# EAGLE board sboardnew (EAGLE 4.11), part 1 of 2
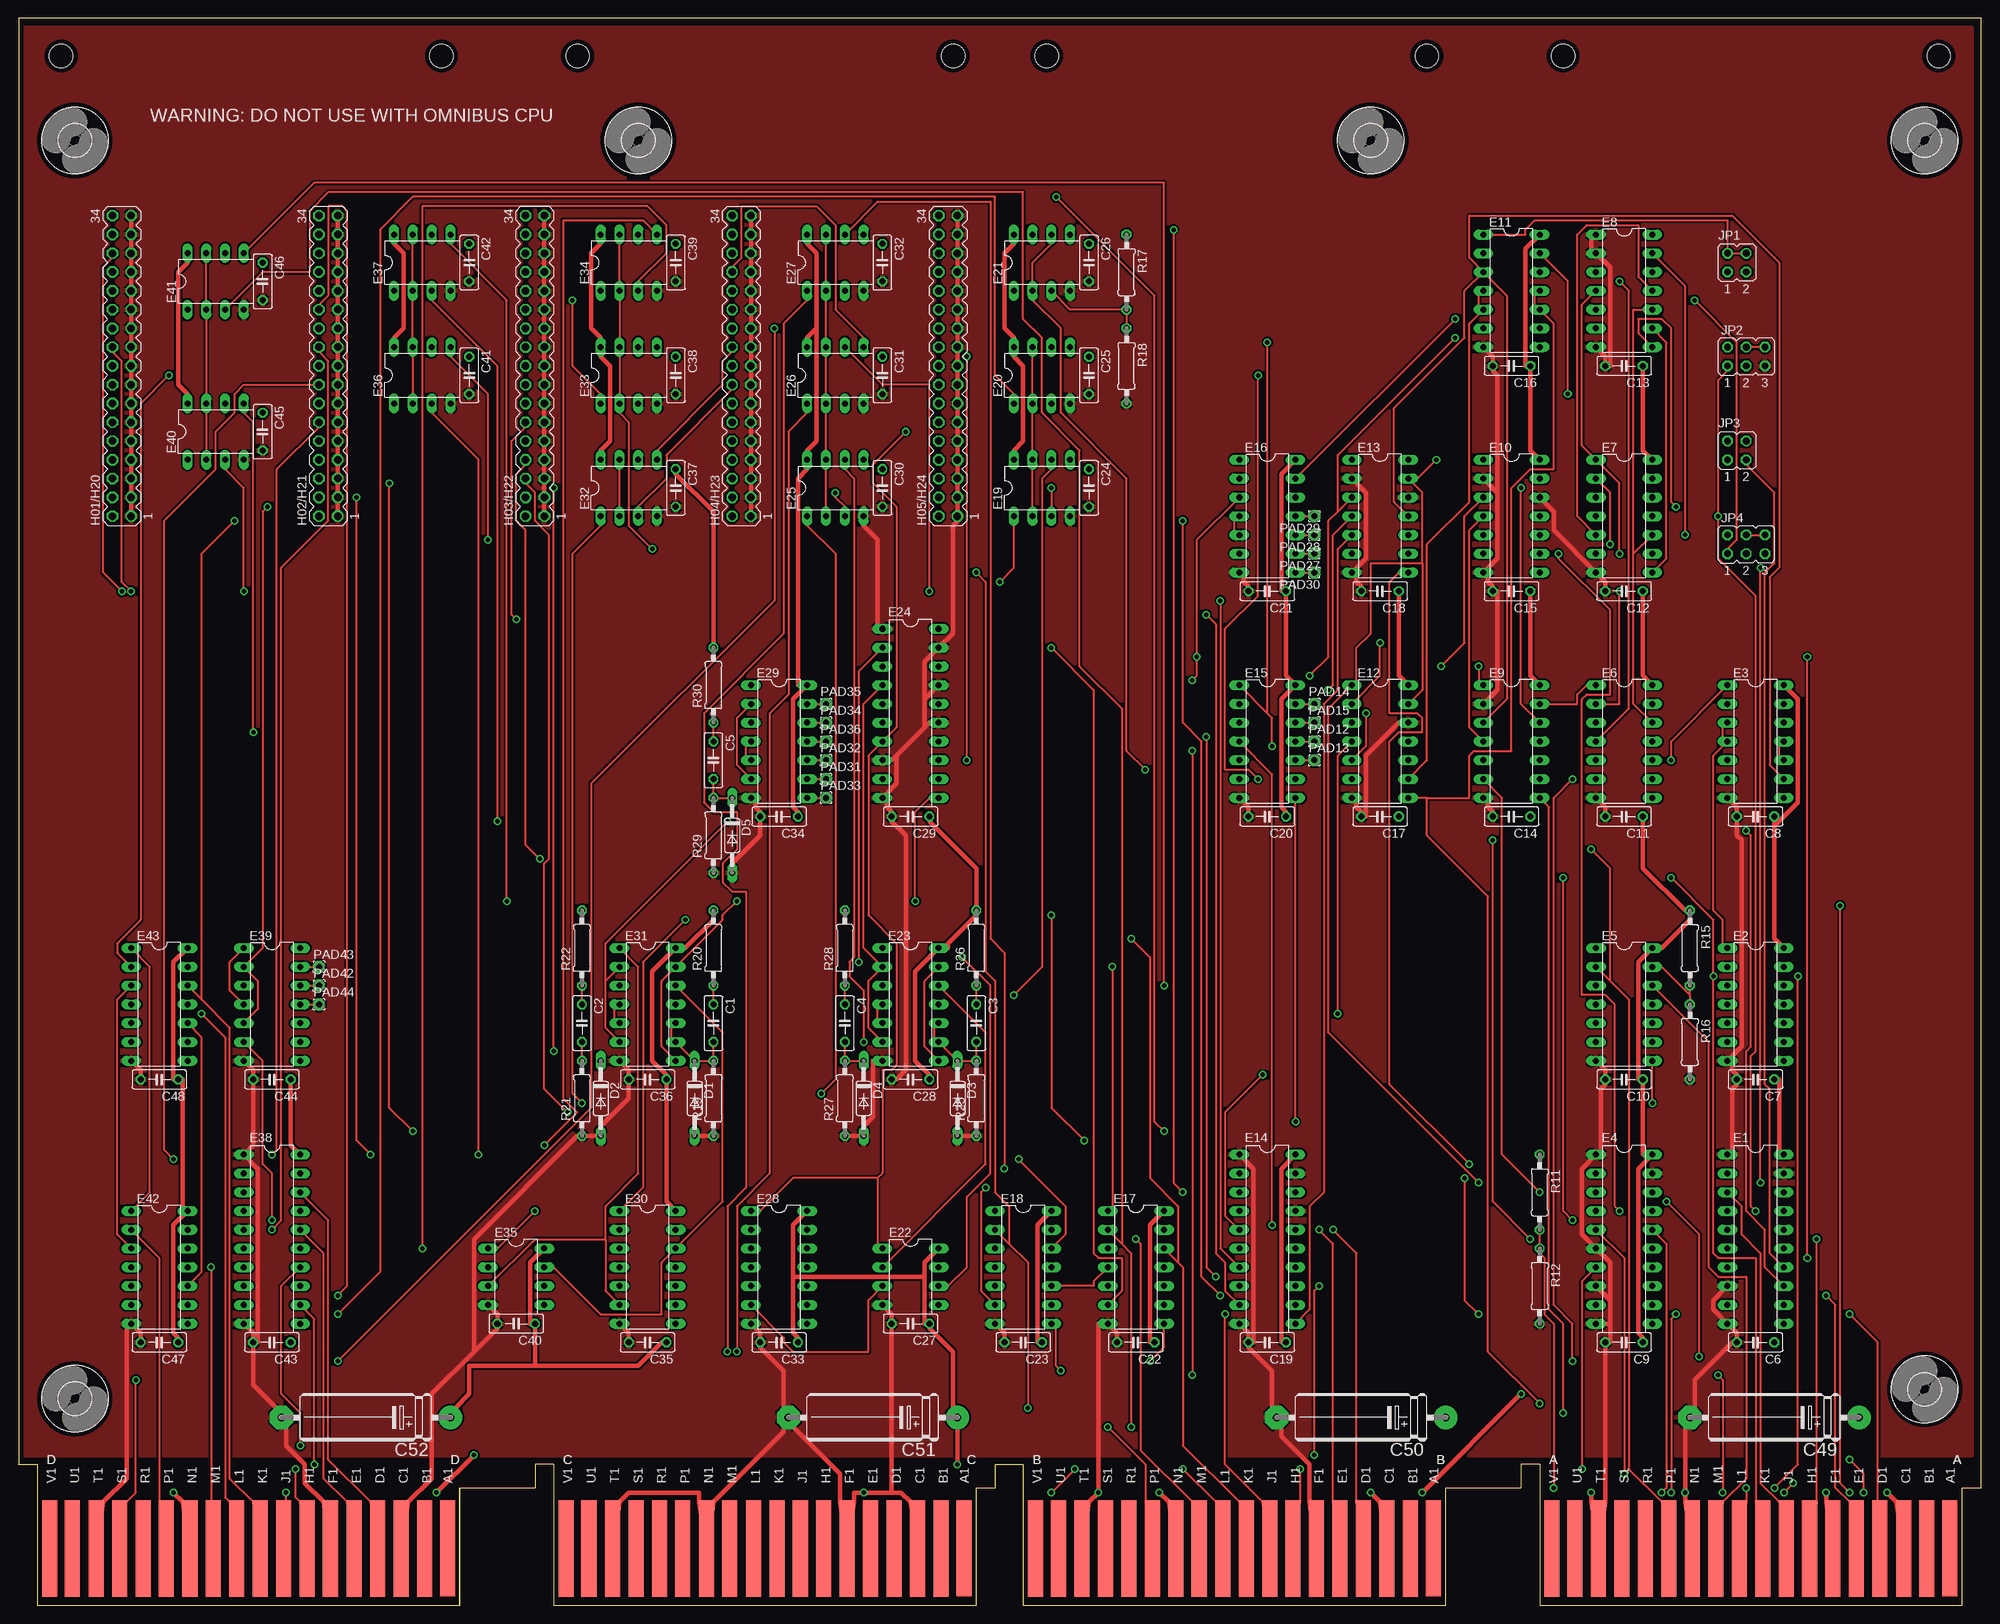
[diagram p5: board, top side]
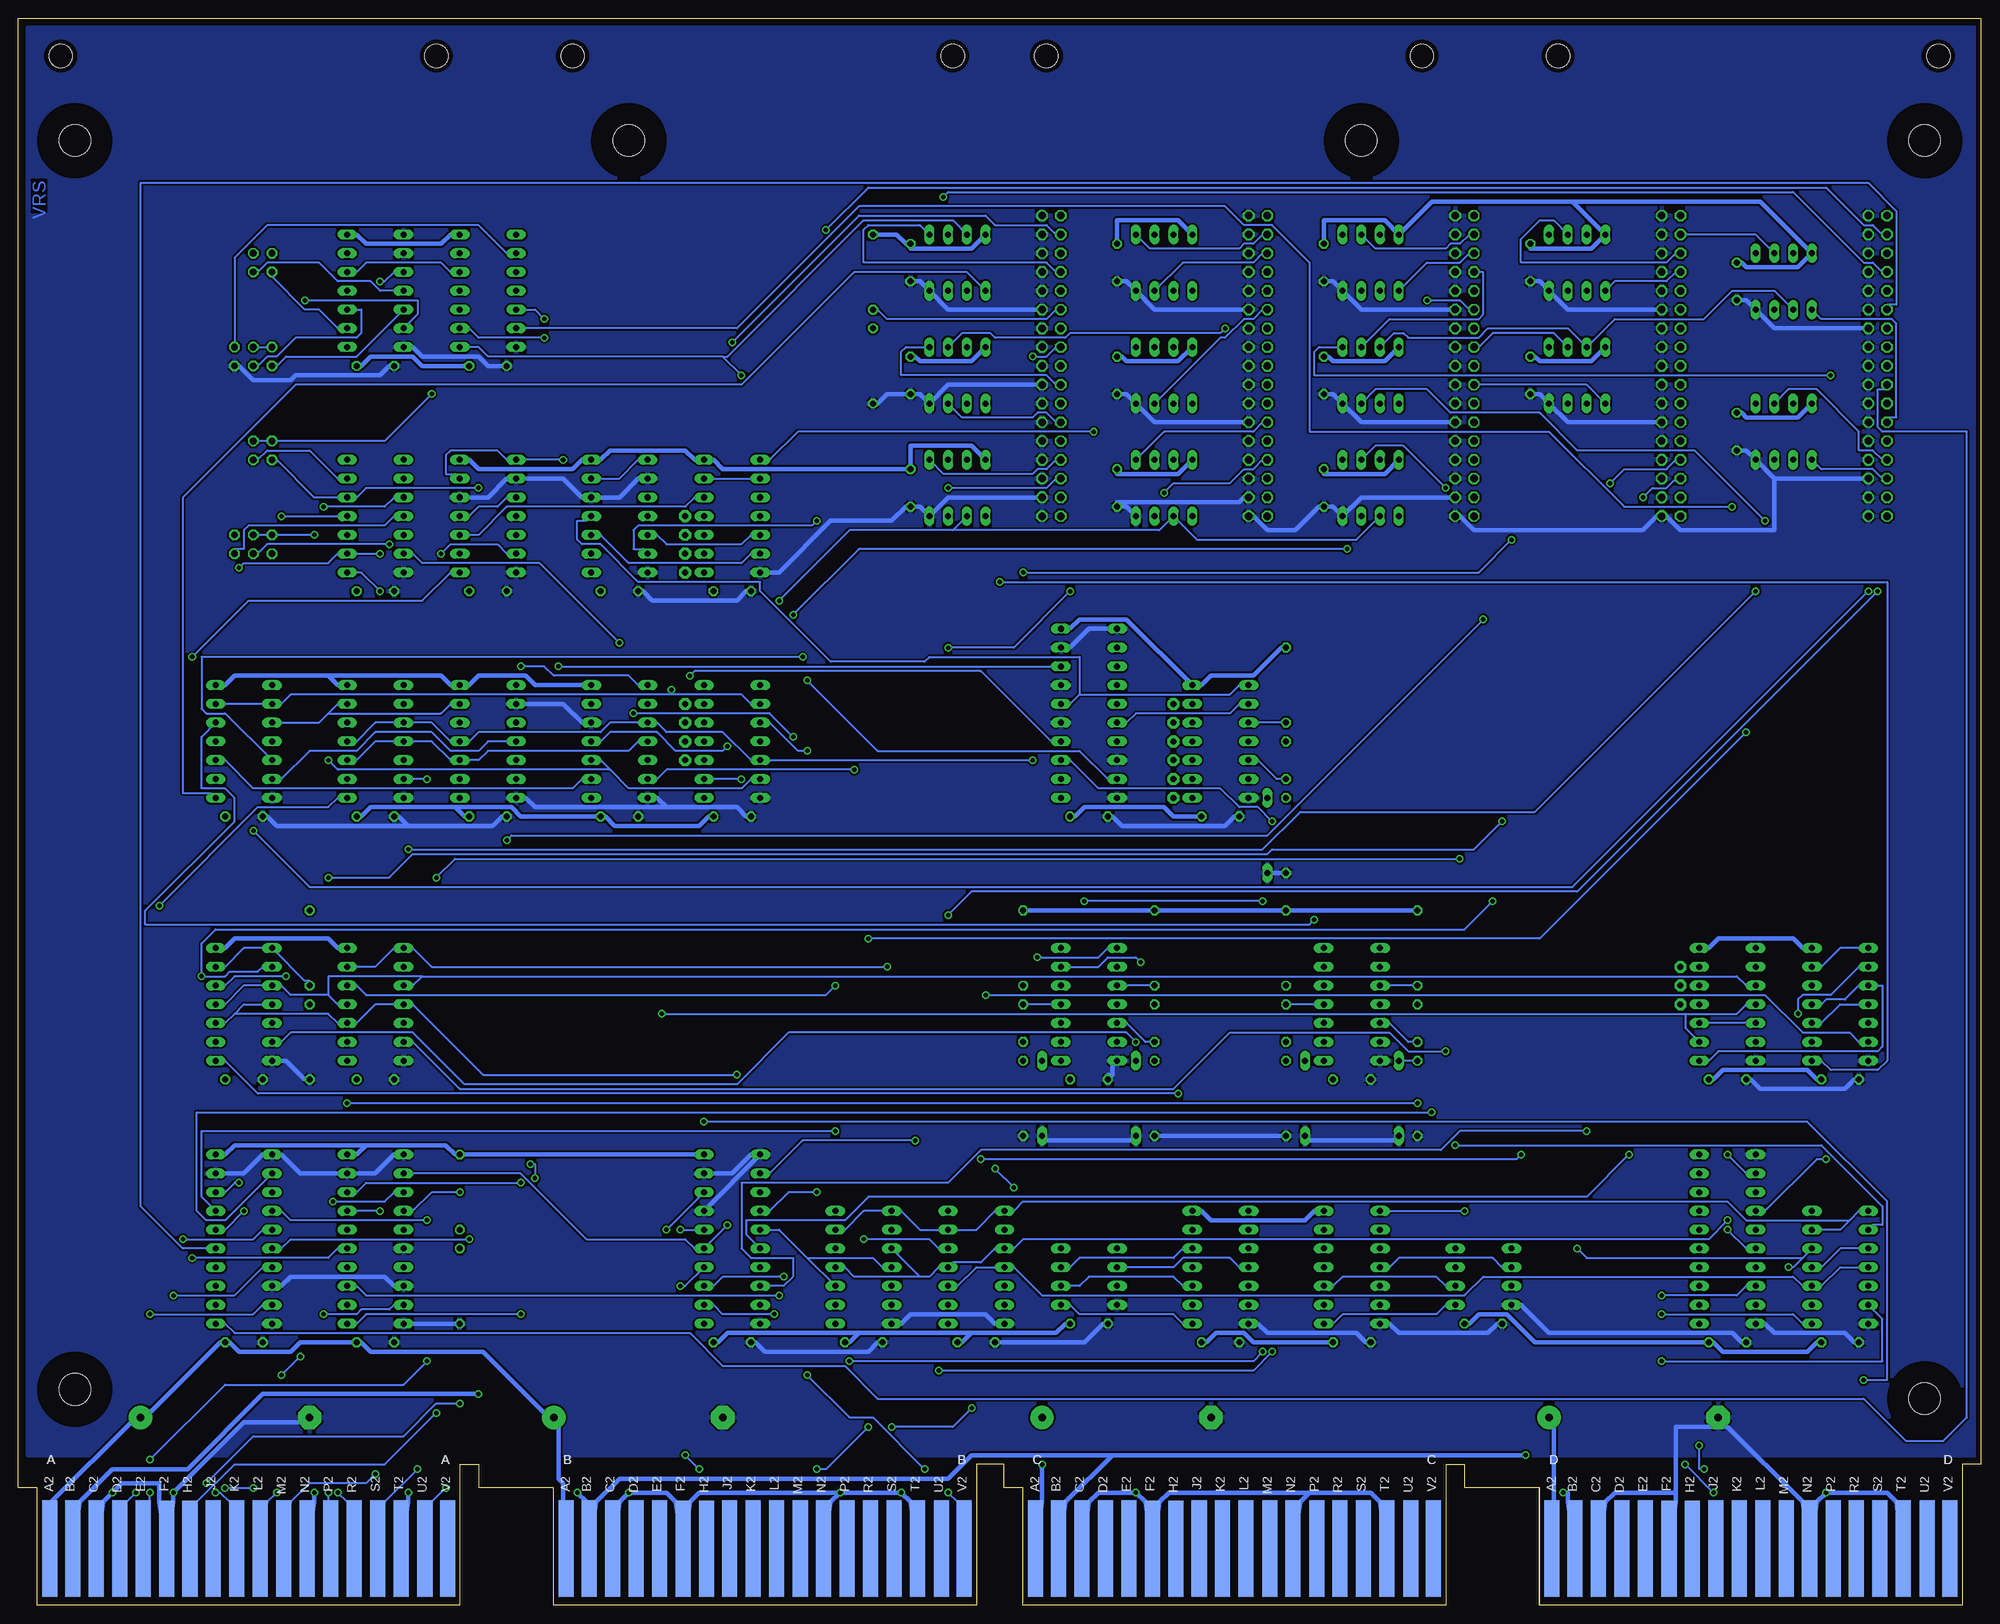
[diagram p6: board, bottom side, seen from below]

Size 265.43 x 214.63 mm. Coordinates in mm from the lower left corner, seen from the top.
Copper layers (1*16): Top 0.035mm / dielectric 1.5mm / Bottom 0.035mm
Design rules "olimex10mil": minimum track width 10mil, minimum drill 24mil, track to track 10mil, track to pad 10mil, pad to pad 10mil, via to via 10mil, smd to smd 10mil, copper to edge 25mil, drill to drill 10mil, minimum pad ring 10mil, minimum via ring 8mil, stop-mask expansion 0mil, vias tented up to drill 0mil, thermal gap 10mil
Net classes: 1 Power: width 0.635 mm

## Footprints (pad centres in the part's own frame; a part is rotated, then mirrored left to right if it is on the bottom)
C050-025X075 = drill 0.813 octagon: 1 -2.54,0; 2 2.54,0
E22-6 = drill 1.016 pad 3.15 round: + -11.43,0 | drill 1.016 pad 3.15 octagon: - 11.43,0
DO35-10 = drill 0.813 long: A 5.08,0; C -5.08,0
DIL20 = drill 0.813 long: 1 -11.43,-3.81; 2 -8.89,-3.81; 3 -6.35,-3.81; 4 -3.81,-3.81; 5 -1.27,-3.81; 6 1.27,-3.81; 7 3.81,-3.81; 8 6.35,-3.81; 9 8.89,-3.81; 10 11.43,-3.81; 11 11.43,3.81; 12 8.89,3.81; 13 6.35,3.81; 14 3.81,3.81; 15 1.27,3.81; 16 -1.27,3.81; 17 -3.81,3.81; 18 -6.35,3.81; 19 -8.89,3.81; 20 -11.43,3.81
DIL14 = drill 0.813 long: 1 -7.62,-3.81; 2 -5.08,-3.81; 3 -2.54,-3.81; 4 0,-3.81; 5 2.54,-3.81; 6 5.08,-3.81; 7 7.62,-3.81; 8 7.62,3.81; 9 5.08,3.81; 10 2.54,3.81; 11 0,3.81; 12 -2.54,3.81; 13 -5.08,3.81; 14 -7.62,3.81
DIL08 = drill 0.813 long: 1 -3.81,-3.81; 2 -1.27,-3.81; 3 1.27,-3.81; 4 3.81,-3.81; 5 3.81,3.81; 6 1.27,3.81; 7 -1.27,3.81; 8 -3.81,3.81
MA17-2 = drill 1.016 octagon: 1 -20.32,-1.27; 2 -20.32,1.27; 3 -17.78,-1.27; 4 -17.78,1.27; 5 -15.24,-1.27; 6 -15.24,1.27; 7 -12.7,-1.27; 8 -12.7,1.27; 9 -10.16,-1.27; 10 -10.16,1.27; 11 -7.62,-1.27; 12 -7.62,1.27; 13 -5.08,-1.27; 14 -5.08,1.27; 15 -2.54,-1.27; 16 -2.54,1.27; 17 0,-1.27; 18 0,1.27; 19 2.54,-1.27; 20 2.54,1.27; 21 5.08,-1.27; 22 5.08,1.27; 23 7.62,-1.27; 24 7.62,1.27; 25 10.16,-1.27; 26 10.16,1.27; 27 12.7,-1.27; 28 12.7,1.27; 29 15.24,-1.27; 30 15.24,1.27; 31 17.78,-1.27; 32 17.78,1.27; 33 20.32,-1.27; 34 20.32,1.27
JP2Q = drill 0.914 octagon: 1 -1.27,-1.27; 2 -1.27,1.27; 3 1.27,-1.27; 4 1.27,1.27
JP3Q = drill 0.914 octagon: 1 -2.54,-1.27; 2 -2.54,1.27; 3 0,-1.27; 4 0,1.27; 5 2.54,-1.27; 6 2.54,1.27
1,6/0,8 = drill 0.813 pad 1.6 octagon: 1 0,0
0207/10 = drill 0.813 octagon: 1 -5.08,0; 2 5.08,0
EDGE-CON8 = smd 2.032 x 13.017: AA1 261.223,7.709; AB1 258.118,7.684; AC1 254.956,7.684; AD1 251.765,7.684; AE1 248.59,7.693; AF1 245.389,7.668; AH1 242.24,7.668; AJ1 239.09,7.668; AK1 235.915,7.668; AL1 232.74,7.693; AM1 229.54,7.693; AN1 226.39,7.693; AP1 223.19,7.668; AR1 220.04,7.668; AS1 216.865,7.693; AT1 213.69,7.693; AU1 210.49,7.693; AV1 207.404,7.668; BA1 191.373,7.709; BB1 188.268,7.684; BC1 185.106,7.684; BD1 181.915,7.684; BE1 178.74,7.693; BF1 175.539,7.668; BH1 172.39,7.668; BJ1 169.24,7.668; BK1 166.065,7.668; BL1 162.89,7.693; BM1 159.69,7.693; BN1 156.54,7.693; BP1 153.34,7.668; BR1 150.19,7.668; BS1 147.015,7.693; BT1 143.84,7.693; BU1 140.64,7.693; BV1 137.554,7.668; CA1 127.873,7.709; CB1 124.768,7.684; CC1 121.606,7.684; CD1 118.415,7.684; CE1 115.24,7.693; CF1 112.039,7.668; CH1 108.89,7.668; CJ1 105.74,7.668; CK1 102.565,7.668; CL1 99.39,7.693; CM1 96.19,7.693; CN1 93.04,7.693; CP1 89.84,7.668; CR1 86.69,7.668; CS1 83.515,7.693; CT1 80.34,7.693; CU1 77.14,7.693; CV1 74.054,7.668; DA1 58.023,7.709; DB1 54.918,7.684; DC1 51.756,7.684; DD1 48.565,7.684; DE1 45.39,7.693; DF1 42.189,7.668; DH1 39.04,7.668; DJ1 35.89,7.668; DK1 32.715,7.668; DL1 29.54,7.693; DM1 26.34,7.693; DN1 23.19,7.693; DP1 19.99,7.668; DR1 16.84,7.668; DS1 13.665,7.693; DT1 10.49,7.693; DU1 7.29,7.693; DV1 4.204,7.668 | smd 2.032 x 13.017 bottom: AA2 261.223,7.69; AB2 258.102,7.668; AC2 254.94,7.668; AD2 251.765,7.693; AE2 248.59,7.693; AF2 245.389,7.642; AH2 242.24,7.642; AJ2 239.09,7.668; AK2 235.915,7.668; AL2 232.74,7.693; AM2 229.54,7.693; AN2 226.39,7.693; AP2 223.19,7.668; AR2 220.04,7.668; AS2 216.865,7.693; AT2 213.69,7.693; AU2 210.464,7.693; AV2 207.404,7.668; BA2 191.373,7.69; BB2 188.252,7.668; BC2 185.09,7.668; BD2 181.915,7.693; BE2 178.74,7.693; BF2 175.539,7.642; BH2 172.39,7.642; BJ2 169.24,7.668; BK2 166.065,7.668; BL2 162.89,7.693; BM2 159.69,7.693; BN2 156.54,7.693; BP2 153.34,7.668; BR2 150.19,7.668; BS2 147.015,7.693; BT2 143.84,7.693; BU2 140.614,7.693; BV2 137.554,7.668; CA2 127.873,7.69; CB2 124.752,7.668; CC2 121.59,7.668; CD2 118.415,7.693; CE2 115.24,7.693; CF2 112.039,7.642; CH2 108.89,7.642; CJ2 105.74,7.668; CK2 102.565,7.668; CL2 99.39,7.693; CM2 96.19,7.693; CN2 93.04,7.693; CP2 89.84,7.668; CR2 86.69,7.668; CS2 83.515,7.693; CT2 80.34,7.693; CU2 77.114,7.693; CV2 74.054,7.668; DA2 58.023,7.69; DB2 54.902,7.668; DC2 51.74,7.668; DD2 48.565,7.693; DE2 45.39,7.693; DF2 42.189,7.642; DH2 39.04,7.642; DJ2 35.89,7.668; DK2 32.715,7.668; DL2 29.54,7.693; DM2 26.34,7.693; DN2 23.19,7.693; DP2 19.99,7.668; DR2 16.84,7.668; DS2 13.665,7.693; DT2 10.49,7.693; DU2 7.264,7.693; DV2 4.204,7.668
OMNIBUS = hole 3.175: 208.915,209.55; 259.715,209.55; 190.5,209.55; 139.065,209.55; 75.616,209.55; 126.416,209.55; 57.201,209.55; 5.766,209.55
4,3 = hole 4.3: 0,0

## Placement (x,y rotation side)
C1  .22uf  [C050-025X075]  93.98,78.74 270 top
C2  .22uf  [C050-025X075]  76.2,78.74 270 top
C3  .22uf  [C050-025X075]  129.54,78.74 270 top
C4  .22uf  [C050-025X075]  111.76,78.74 270 top
C5  .22uf  [C050-025X075]  93.98,114.3 270 top
C6  [C050-025X075]  234.95,35.56 180 top
C7  [C050-025X075]  234.95,71.12 180 top
C8  [C050-025X075]  234.95,106.68 180 top
C9  [C050-025X075]  217.17,35.56 180 top
C10  [C050-025X075]  217.17,71.12 180 top
C11  [C050-025X075]  217.17,106.68 180 top
C12  [C050-025X075]  217.17,137.16 180 top
C13  [C050-025X075]  217.17,167.64 180 top
C14  [C050-025X075]  201.93,106.68 180 top
C15  [C050-025X075]  201.93,137.16 180 top
C16  [C050-025X075]  201.93,167.64 180 top
C17  [C050-025X075]  184.15,106.68 180 top
C18  [C050-025X075]  184.15,137.16 180 top
C19  [C050-025X075]  168.91,35.56 180 top
C20  [C050-025X075]  168.91,106.68 180 top
C21  [C050-025X075]  168.91,137.16 180 top
C22  [C050-025X075]  151.13,35.56 180 top
C23  [C050-025X075]  135.89,35.56 180 top
C24  [C050-025X075]  144.78,151.13 270 top
C25  [C050-025X075]  144.78,166.37 270 top
C26  [C050-025X075]  144.78,181.61 270 top
C27  [C050-025X075]  120.65,38.1 180 top
C28  [C050-025X075]  120.65,71.12 180 top
C29  [C050-025X075]  120.65,106.68 180 top
C30  [C050-025X075]  116.84,151.13 270 top
C31  [C050-025X075]  116.84,166.37 270 top
C32  [C050-025X075]  116.84,181.61 270 top
C33  [C050-025X075]  102.87,35.56 180 top
C34  [C050-025X075]  102.87,106.68 180 top
C35  [C050-025X075]  85.09,35.56 180 top
C36  [C050-025X075]  85.09,71.12 180 top
C37  [C050-025X075]  88.9,151.13 270 top
C38  [C050-025X075]  88.9,166.37 270 top
C39  [C050-025X075]  88.9,181.61 270 top
C40  [C050-025X075]  67.31,38.1 180 top
C41  [C050-025X075]  60.96,166.37 270 top
C42  [C050-025X075]  60.96,181.61 270 top
C43  [C050-025X075]  34.29,35.56 180 top
C44  [C050-025X075]  34.29,71.12 180 top
C45  [C050-025X075]  33.02,158.75 270 top
C46  [C050-025X075]  33.02,179.07 270 top
C47  [C050-025X075]  19.05,35.56 180 top
C48  [C050-025X075]  19.05,71.12 180 top
C49  [E22-6]  237.49,25.4 180 top
C50  [E22-6]  181.61,25.4 180 top
C51  [E22-6]  115.57,25.4 180 top
C52  [E22-6]  46.99,25.4 180 top
D1  1N4148  [DO35-10]  91.44,68.58 270 top
D2  1N4148  [DO35-10]  78.74,68.58 270 top
D3  1N4148  [DO35-10]  127,68.58 270 top
D4  1N4148  [DO35-10]  114.3,68.58 270 top
D5  1N4148  [DO35-10]  96.52,104.14 270 top
E1  74S240N  [DIL20]  234.95,49.53 270 top
E2  74S74N  [DIL14]  234.95,81.28 270 top
E3  7410N  [DIL14]  234.95,116.84 270 top
E4  74S240N  [DIL20]  217.17,49.53 270 top
E5  74S74N  [DIL14]  217.17,81.28 270 top
E6  74S74N  [DIL14]  217.17,116.84 270 top
E7  7404N  [DIL14]  217.17,147.32 270 top
E8  7400N  [DIL14]  217.17,177.8 270 top
E9  74S74N  [DIL14]  201.93,116.84 270 top
E10  74S74N  [DIL14]  201.93,147.32 270 top
E11  7410N  [DIL14]  201.93,177.8 270 top
E12  74S74N  [DIL14]  184.15,116.84 270 top
E13  74S74N  [DIL14]  184.15,147.32 270 top
E14  74S240N  [DIL20]  168.91,49.53 270 top
E15  7404N  [DIL14]  168.91,116.84 270 top
E16  7410N  [DIL14]  168.91,147.32 270 top
E17  74S74N  [DIL14]  151.13,45.72 270 top
E18  74S74N  [DIL14]  135.89,45.72 270 top
E19  DS75453N  [DIL08]  138.43,151.13 0 top
E20  DS75453N  [DIL08]  138.43,166.37 0 top
E21  DS75453N  [DIL08]  138.43,181.61 0 top
E22  DS1100M-250  [DIL08]  120.65,44.45 270 top
E23  7400N  [DIL14]  120.65,81.28 270 top
E24  74S240N  [DIL20]  120.65,120.65 270 top
E25  DS75453N  [DIL08]  110.49,151.13 0 top
E26  DS75453N  [DIL08]  110.49,166.37 0 top
E27  DS75453N  [DIL08]  110.49,181.61 0 top
E28  DS1005-250  [DIL14]  102.87,45.72 270 top
E29  7400N  [DIL14]  102.87,116.84 270 top
E30  DS1005-250  [DIL14]  85.09,45.72 270 top
E31  7400N  [DIL14]  85.09,81.28 270 top
E32  DS75453N  [DIL08]  82.55,151.13 0 top
E33  DS75453N  [DIL08]  82.55,166.37 0 top
E34  DS75453N  [DIL08]  82.55,181.61 0 top
E35  DS1100M-250  [DIL08]  67.31,44.45 270 top
E36  DS75453N  [DIL08]  54.61,166.37 0 top
E37  DS75453N  [DIL08]  54.61,181.61 0 top
E38  74S240N  [DIL20]  34.29,49.53 270 top
E39  7400N  [DIL14]  34.29,81.28 270 top
E40  DS75453N  [DIL08]  26.67,158.75 0 top
E41  DS75453N  [DIL08]  26.67,179.07 0 top
E42  74S74N  [DIL14]  19.05,45.72 270 top
E43  74S74N  [DIL14]  19.05,81.28 270 top
H01/H20  [MA17-2]  13.97,167.64 90 top
H02/H21  [MA17-2]  41.91,167.64 90 top
H03/H22  [MA17-2]  69.85,167.64 90 top
H04/H23  [MA17-2]  97.79,167.64 90 top
H05/H24  [MA17-2]  125.73,167.64 90 top
JP1  [JP2Q]  232.41,181.61 0 top
JP2  [JP3Q]  233.68,168.91 0 top
JP3  [JP2Q]  232.41,156.21 0 top
JP4  [JP3Q]  233.68,143.51 0 top
PAD12  [1,6/0,8]  175.26,116.84 0 top
PAD13  [1,6/0,8]  175.26,114.3 0 top
PAD14  [1,6/0,8]  175.26,121.92 0 top
PAD15  [1,6/0,8]  175.26,119.38 0 top
PAD27  [1,6/0,8]  175.26,142.24 180 top
PAD28  [1,6/0,8]  175.26,144.78 180 top
PAD29  [1,6/0,8]  175.26,147.32 180 top
PAD30  [1,6/0,8]  175.26,139.7 180 top
PAD31  [1,6/0,8]  109.22,111.76 0 top
PAD32  [1,6/0,8]  109.22,114.3 0 top
PAD33  [1,6/0,8]  109.22,109.22 0 top
PAD34  [1,6/0,8]  109.22,119.38 0 top
PAD35  [1,6/0,8]  109.22,121.92 0 top
PAD36  [1,6/0,8]  109.22,116.84 0 top
PAD42  [1,6/0,8]  40.64,83.82 0 top
PAD43  [1,6/0,8]  40.64,86.36 0 top
PAD44  [1,6/0,8]  40.64,81.28 0 top
R11  330  [0207/10]  205.74,55.88 270 top
R12  750  [0207/10]  205.74,43.18 270 top
R15  330  [0207/10]  226.06,88.9 270 top
R16  750  [0207/10]  226.06,76.2 270 top
R17  330  [0207/10]  149.86,180.34 270 top
R18  750  [0207/10]  149.86,167.64 270 top
R19  330  [0207/10]  93.98,68.58 90 top
R20  330  [0207/10]  93.98,88.9 90 top
R21  330  [0207/10]  76.2,68.58 90 top
R22  330  [0207/10]  76.2,88.9 90 top
R25  330  [0207/10]  129.54,68.58 90 top
R26  330  [0207/10]  129.54,88.9 90 top
R27  330  [0207/10]  111.76,68.58 90 top
R28  330  [0207/10]  111.76,88.9 90 top
R29  330  [0207/10]  93.98,104.14 90 top
R30  330  [0207/10]  93.98,124.46 90 top
U$1  [EDGE-CON8]  0,0 0 top
U$2  OUTLINE-OMNIBUS  [OMNIBUS]  0,0 0 top
U$20  [4,3]  257.81,198.12 270 top
U$66  [4,3]  83.82,198.12 270 top
U$67  [4,3]  182.88,198.12 270 top
U$82  [4,3]  257.81,29.21 270 top
U$83  [4,3]  7.62,27.94 270 top
U$86  [4,3]  7.62,198.12 270 top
